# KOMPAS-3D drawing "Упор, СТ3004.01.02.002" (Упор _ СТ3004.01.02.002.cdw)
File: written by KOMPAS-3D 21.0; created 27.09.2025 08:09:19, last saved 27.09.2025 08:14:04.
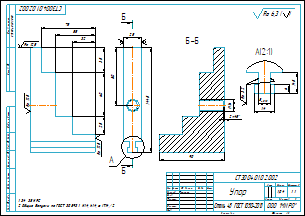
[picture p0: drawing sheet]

Sheet 1: A3, landscape

Document properties: Полное имя файла: C:\Users\Lutik\Yandex.Disk\Документы\Новая папка\Стапель №2\Стапель _ СТ3004.00.00.000\Опора _ СТ3004.01.00.000\2D\Кронштейн _ СТ3004.01.02.000\Упор _ СТ3004.01.02.002.cdw; Знак неуказанной шероховатости: 4; Параметр неуказанной шероховатости: Ra 6,3; Масса: 1.036373

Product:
- Part/product: Упор  | designation СТ3004.01.02.002
    Материал: Сталь 45  ГОСТ 1050-2013 (density 7810 kg/m3)
    Масса: 1.036373

Title block, sheet 1: Наименование: Упор; designation: СТ3004.01.02.002; Материал: Сталь 45  ГОСТ 1050-2013; Масса: 1,04; Количество листов документа: 1; organisation: ООО "МИРО"; Форматы листов документа: A3; Разработал: Тимонин

Views: Вид 1, Спереди, Проекционный вид 2, Разрез А-А, Выносной элемент 4, Разрез Б-Б, Выносной элемент А, Выносной элемент
Referenced files in C:\Users\Lutik\Yandex.Disk\Документы\Новая папка\Стапель №2\Стапель _ СТ3004.00.00.000\Опора _ СТ3004.01.00.000\3D\Кронштейн _ СТ3004.01.02.000\: Упор _ СТ3004.01.02.002.m3d
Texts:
  Ra 12,5
  Ra 3,2
  Ra 6,3
  Ra 6,3 ( )
  СТ3004.01.02.000
  СТ3004.01.02.002 Упор
Dimensions and other numbers on the sheet: 32; 55; 75; 25; 60; 35; 80; 144,5; 16; 2; 90; 8; 14; 14,5; 6; 1:1; 1; 1,04

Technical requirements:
  34...38 HRC.
  Общие допуски по ГОСТ 30893.1: Н14, h14, ± IT14/2.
